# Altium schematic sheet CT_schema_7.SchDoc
size 368 x 245 mm
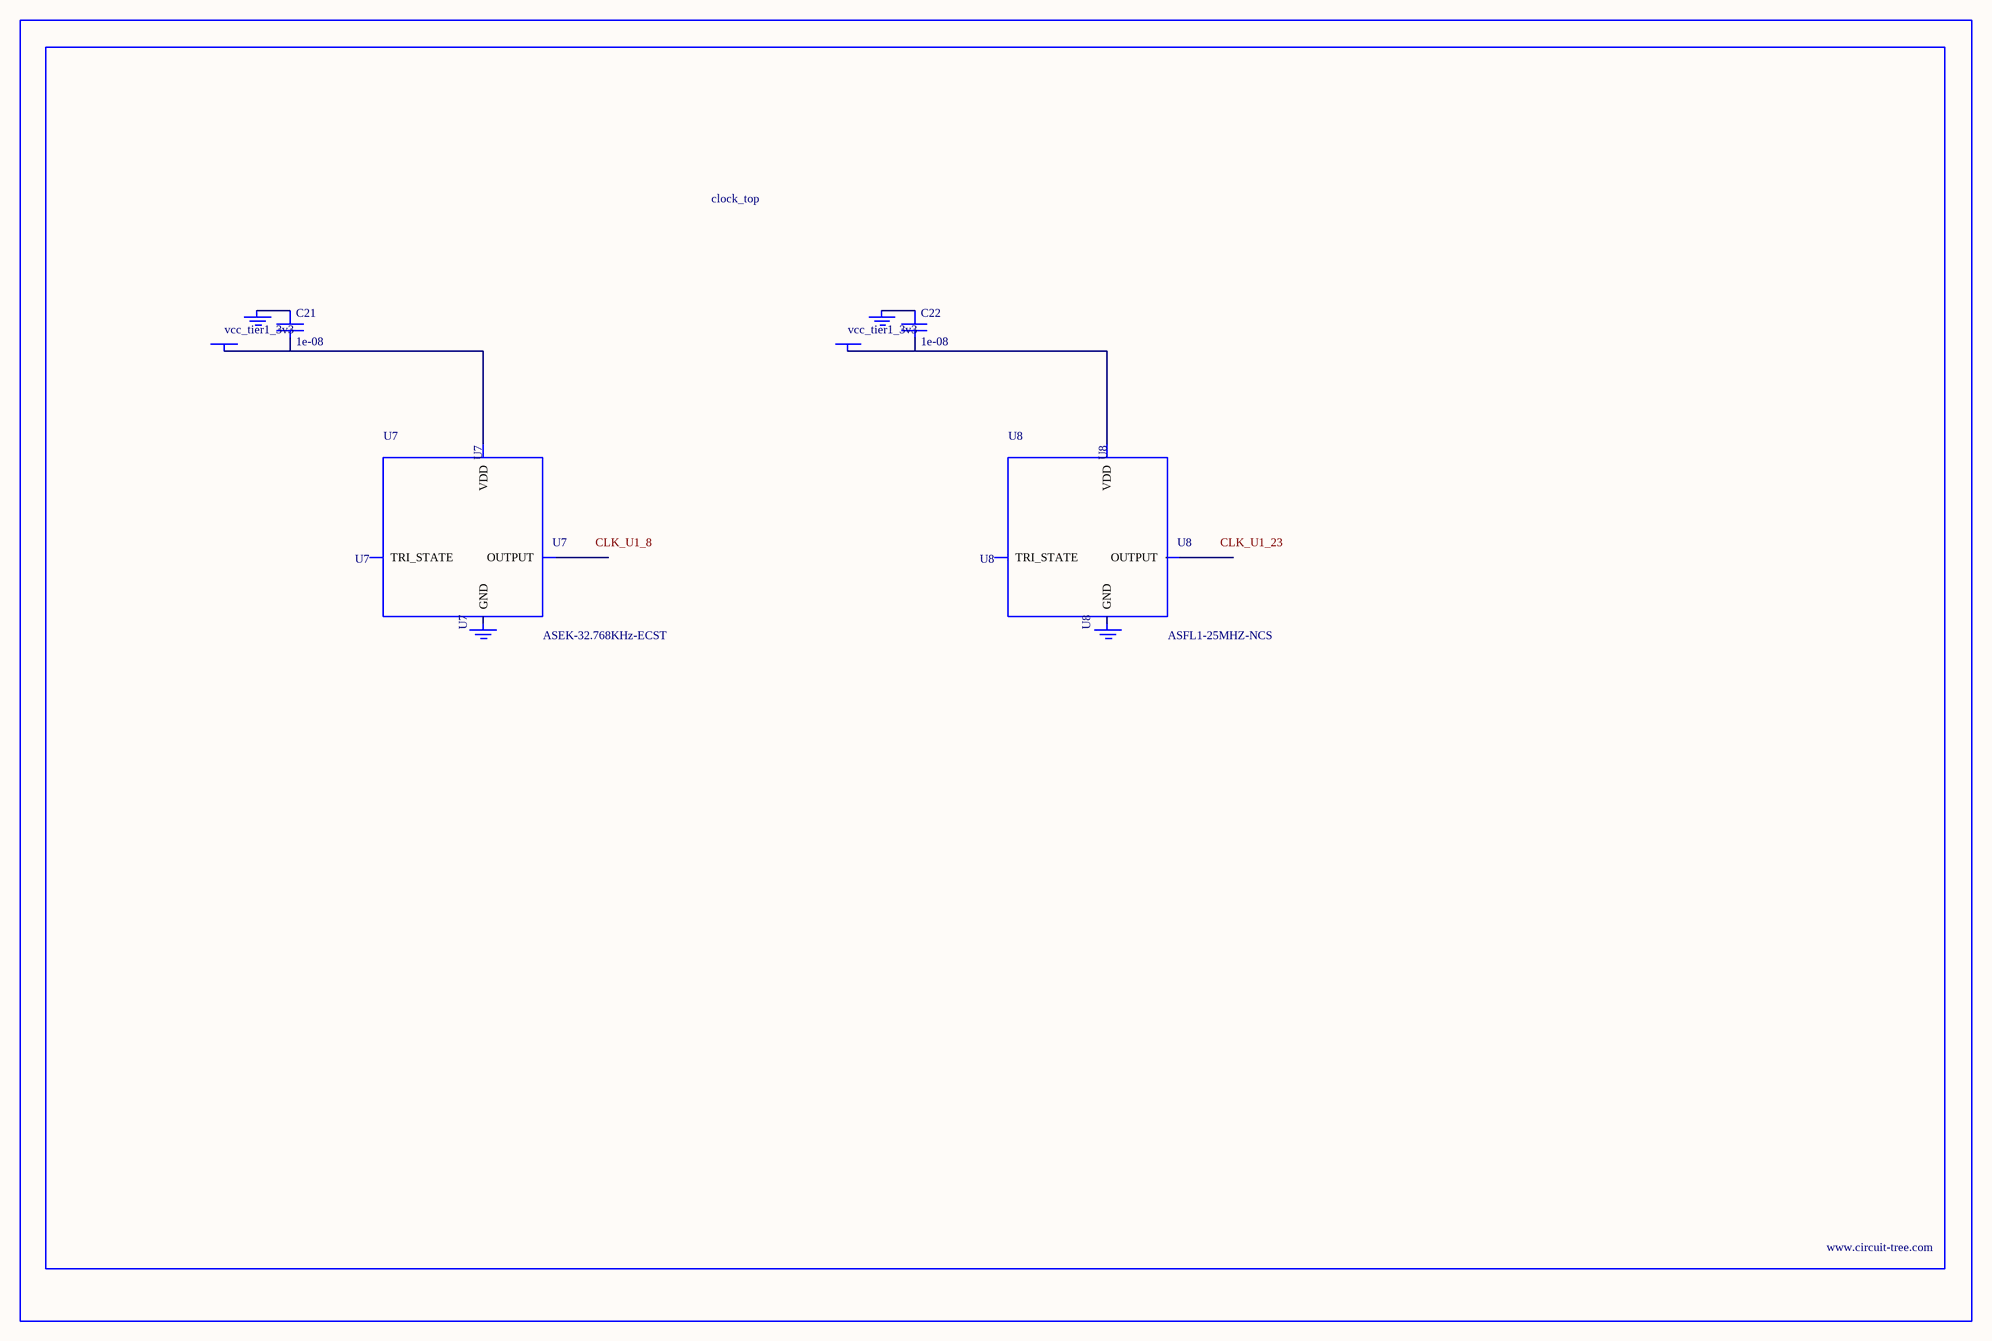
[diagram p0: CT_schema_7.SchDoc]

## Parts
BORDER6  (no value)
C21  1e-08  [C0402]
C22  1e-08  [C0402]
GND_INSTANCE_6_0  (no value)
GND_INSTANCE_6_1  (no value)
GND_INSTANCE_6_2  (no value)
GND_INSTANCE_6_3  (no value)
POWER_INSTANCE_6_0  vcc_tier1_3v3
POWER_INSTANCE_6_1  vcc_tier1_3v3
U7  ASEK-32.768KHz-ECST  [ASEK]
U8  ASFL1-25MHZ-NCS  [ASFL1]

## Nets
NetC21_1: C21.1 GND_INSTANCE_6_0.0(GND)
NetC21_2: C21.2 POWER_INSTANCE_6_0.0(PWR) U7.4(VDD)
NetC22_1: C22.1 GND_INSTANCE_6_2.0(GND)
NetC22_2: C22.2 POWER_INSTANCE_6_1.0(PWR) U8.4(VDD)

Not connected (* = marked no-connect by the designer): GND_INSTANCE_6_1 0(GND); GND_INSTANCE_6_3 0(GND); U7 1(TRI_STATE) 2(GND) 3(OUTPUT); U8 1(TRI_STATE) 2(GND) 3(OUTPUT)

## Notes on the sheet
- Labels drawn without touching a wire or pin: CLK_U1_8, CLK_U1_23

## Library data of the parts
BORDER6 = BORDER_PAGE6
C21 C22 = C0402C103K3RAC
GND_INSTANCE_6_0-GND_INSTANCE_6_3 = GND
POWER_INSTANCE_6_0 POWER_INSTANCE_6_1 = PWR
